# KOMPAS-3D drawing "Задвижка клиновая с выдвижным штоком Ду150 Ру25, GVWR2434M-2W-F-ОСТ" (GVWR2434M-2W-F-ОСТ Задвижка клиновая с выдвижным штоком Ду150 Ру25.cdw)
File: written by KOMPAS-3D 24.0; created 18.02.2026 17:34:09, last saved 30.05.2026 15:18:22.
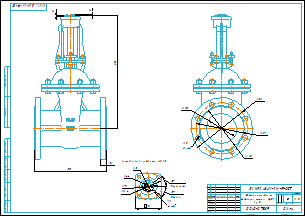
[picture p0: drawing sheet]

Document properties: art: D040-10013; Автор: R2D2; Форматы листов документа: A2; Полное имя файла: GVWR2434M-2W-F-ОСТ Задвижка клиновая с выдвижным штоком Ду150 Ру25.m3d; Масса: 60; Наименование: Задвижка клиновая с выдвижным штоком Ду150 Ру25; Количество листов документа: 1; Примечание: D040-07589

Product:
- Part/product: Задвижка клиновая с выдвижным штоком Ду150 Ру25  | designation GVWR2434M-2W-F-ОСТ
    Масса: 60
    Раздел спецификации: Прочие изделия
    Примечание: D040-07589
    additional columns: D040-10013

Views: Проекционный вид 3
Referenced files in E:\Работа\Зайцев\Для компаса\: чертеж DN.ru А3.cdt
Referenced files in E:\Работа\Зайцев\GVWR2434M-2W-F-ОСТ Задвижка клиновая с выдвижным штоком DN.ru Ду50-300 Ру25\исходные материалы\DN150\DN150\: GVWR2434M-2W-F-ОСТ Задвижка клиновая с выдвижным штоком Ду150 Ру25.m3d
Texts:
  Присоединение привода тип АК (А)
  чертеж DN.ru А3.cdt
  Задвижка клиновая с
  выдвижным штоком Ду150
  Ру25
  GVWR2434M-2W-F-ОСТ
  Задвижка клиновая с выдвижным штоком Ду150 Ру25
  GVWR2434M-2W-F-ОСТ Задвижка клиновая с выдвижным штоком Ду150 Ру25
Dimensions and other numbers on the sheet: 100; 5 кулачков; 5 впадин; 12; 4 отв.; 104; 70; 44; 32; 1:2,5; 0; 1; 2; 60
